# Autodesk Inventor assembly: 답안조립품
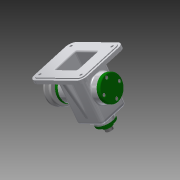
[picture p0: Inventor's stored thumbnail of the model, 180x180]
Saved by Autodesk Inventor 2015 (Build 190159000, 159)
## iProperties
Created: 2016-02
Part Number: 답안조립품
Document SubType Name: Assembly
Designer: Administrator
Author: Administrator
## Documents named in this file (19)
- C:\Users\Administrator\Desktop\460219V1017\답안조립품.iam
- C:\Users\Administrator\Desktop\460219V1017\고정핀.ipt
- C:\Users\Administrator\Desktop\460219V1017\뒤커버.ipt
- C:\Users\Administrator\Desktop\460219V1017\V-벨트풀리.ipt
- C:\Users\Administrator\Desktop\460219V1017\링크.ipt
- C:\Users\Administrator\Desktop\460219V1017\멈춤링 6 x 5.ipt
- C:\Users\Administrator\Desktop\460219V1017\멈춤링 15 x 1.ipt
- C:\Users\Administrator\Desktop\460219V1017\베어링 15 x 35 x 11.ipt
- C:\Users\Administrator\Desktop\460219V1017\본체.ipt
- C:\Users\Administrator\Desktop\460219V1017\볼트 M3 x 8.ipt
- C:\Users\Administrator\Desktop\460219V1017\볼트 M4 x 10.ipt
- C:\Users\Administrator\Desktop\460219V1017\볼트 M6 x 12.ipt
- C:\Users\Administrator\Desktop\460219V1017\상부부시.ipt
- C:\Users\Administrator\Desktop\460219V1017\슬라이드바.ipt
- C:\Users\Administrator\Desktop\460219V1017\앞커버.ipt
- C:\Users\Administrator\Desktop\460219V1017\오일실 15 25 7.ipt
- C:\Users\Administrator\Desktop\460219V1017\와셔.ipt
- C:\Users\Administrator\Desktop\460219V1017\키 5 x 5 x 14.ipt
- C:\Users\Administrator\Desktop\460219V1017\편심축.ipt
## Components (15 placed, 5 different names)
1. 고정핀:1
2. V-벨트풀리:1
3. ISO 4018 M6 x 12:1
4. ISO 4762 M4 x 10:1
5. ISO 4762 M4 x 10:3
6. ISO 4762 M4 x 10:4
7. ISO 4762 M4 x 10:5
8. ISO 4762 M4 x 10:2
9. ISO 4762 M4 x 10:6
10. ISO 4762 M4 x 10:7
11. ISO 4762 M4 x 10:8
12. ISO 4762 M3 x 8:1
13. ISO 4762 M3 x 8:2
14. ISO 4762 M3 x 8:3
15. ISO 4762 M3 x 8:4
